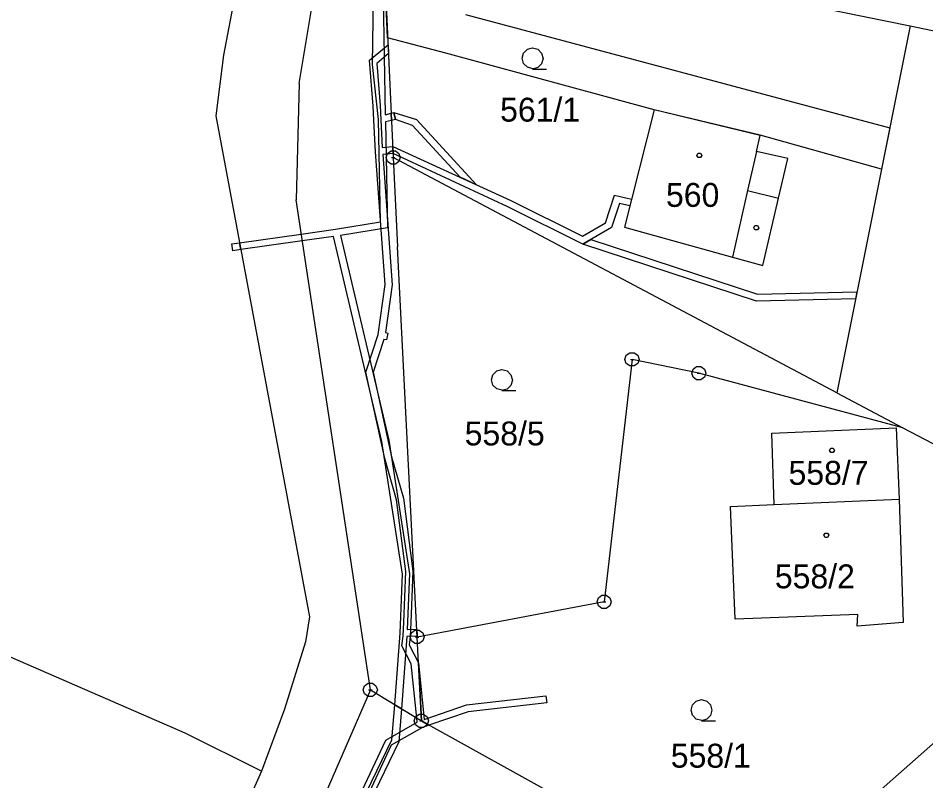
# Model space of a CAD drawing. Extents: x -759699 to -757730, y -1172308 to -1170857.
# Drawn here: x -759235.7 to -759171.2, y -1171629.6 to -1171575.4 of the extents above; entities that cross this region are included whole.
import ezdxf

# ---------------------------------------------------------------- set-up
doc = ezdxf.new("R2010")
doc.units = 0
for name, color, linetype in [('Vrstva 1', 7, 'Continuous'), ('Vrstva 12', 7, 'Continuous'), ('Vrstva 13', 7, 'Continuous'), ('Vrstva 2', 7, 'Continuous'), ('Vrstva 3', 7, 'Continuous'), ('Vrstva 4', 7, 'Continuous'), ('Vrstva 5', 7, 'Continuous'), ('Vrstva 8', 7, 'Continuous')]:
    doc.layers.add(name, color=color, linetype=linetype)

msp = doc.modelspace()

# ---------------------------------------------------------------- linework, layer by layer
at = {"layer": 'Vrstva 1'}
for p, q in [((-759215.76, -1171580.02), (-759212.95, -1171563.14)), ((-759209.89, -1171567.64), (-759209.07, -1171585.28)), ((-759188.19, -1171572.67), (-759172.32, -1171575.91)), ((-759220.33, -1171573.68), (-759221.15, -1171578)), ((-759172.32, -1171575.91), (-759177.54, -1171601.99)), ((-759172.32, -1171575.91), (-759169.31, -1171576.53)), ((-759221.15, -1171578), (-759221.68, -1171582.31)), ((-759215.76, -1171580.02), (-759215.98, -1171588.27)), ((-759190.52, -1171581.89), (-759192.62, -1171590.23)), ((-759182.99, -1171583.71), (-759190.52, -1171581.89)), ((-759221.68, -1171582.31), (-759215.03, -1171617.92)), ((-759183.25, -1171584.85), (-759182.99, -1171583.71)), ((-759209.07, -1171585.28), (-759208.77, -1171591.63)), ((-759177.54, -1171601.99), (-759209.07, -1171585.28)), ((-759181.01, -1171585.35), (-759183.25, -1171584.85)), ((-759181.67, -1171588.17), (-759181.01, -1171585.35)), ((-759210.7, -1171623.12), (-759215.98, -1171588.27)), ((-759182.78, -1171592.95), (-759181.67, -1171588.17)), ((-759192.62, -1171590.23), (-759184.96, -1171592.35)), ((-759207.37, -1171619.36), (-759208.77, -1171591.63)), ((-759184.96, -1171592.35), (-759182.78, -1171592.95)), ((-759192.09, -1171599.63), (-759194.07, -1171616.87)), ((-759187.34, -1171600.61), (-759192.09, -1171599.63)), ((-759172.84, -1171604.48), (-759187.34, -1171600.61)), ((-759177.54, -1171601.99), (-759172.84, -1171604.48)), ((-759182.15, -1171604.87), (-759173.32, -1171604.49)), ((-759173.32, -1171604.49), (-759173.1, -1171609.56)), ((-759172.84, -1171604.48), (-759155.62, -1171613.61)), ((-759181.99, -1171609.94), (-759182.15, -1171604.87)), ((-759223.87, -1171626.2), (-759264.92, -1171608.32)), ((-759181.99, -1171609.94), (-759173.1, -1171609.56)), ((-759173.1, -1171609.56), (-759172.82, -1171618.32)), ((-759185.09, -1171610.07), (-759181.99, -1171609.94)), ((-759184.77, -1171618.09), (-759185.09, -1171610.07)), ((-759183.56, -1171638.31), (-759155.62, -1171613.61)), ((-759194.07, -1171616.87), (-759207.37, -1171619.36)), ((-759215.03, -1171617.92), (-759215.32, -1171619.71)), ((-759176.04, -1171617.76), (-759184.77, -1171618.09)), ((-759176.08, -1171618.59), (-759176.04, -1171617.76)), ((-759172.82, -1171618.32), (-759176.08, -1171618.59)), ((-759207.07, -1171625.33), (-759207.37, -1171619.36)), ((-759215.32, -1171619.71), (-759216.8, -1171624.5)), ((-759210.7, -1171623.12), (-759215.69, -1171634.65)), ((-759210.7, -1171623.12), (-759207.07, -1171625.33)), ((-759216.8, -1171624.5), (-759218.43, -1171628.89)), ((-759207.07, -1171625.33), (-759183.56, -1171638.31)), ((-759218.43, -1171628.89), (-759223.87, -1171626.2)), ((-759218.43, -1171628.89), (-759222.99, -1171638.88))]:
    msp.add_line(p, q, dxfattribs=at)
at = {"layer": 'Vrstva 12'}
for p, q in [((-759190.52, -1171581.89), (-759192.62, -1171590.23)), ((-759182.99, -1171583.71), (-759190.52, -1171581.89)), ((-759183.25, -1171584.85), (-759182.99, -1171583.71)), ((-759183.25, -1171584.85), (-759183.88, -1171587.61)), ((-759183.88, -1171587.61), (-759184.96, -1171592.35)), ((-759192.62, -1171590.23), (-759184.96, -1171592.35)), ((-759182.15, -1171604.87), (-759173.32, -1171604.49)), ((-759173.32, -1171604.49), (-759173.1, -1171609.56)), ((-759181.99, -1171609.94), (-759182.15, -1171604.87)), ((-759181.99, -1171609.94), (-759173.1, -1171609.56)), ((-759181.99, -1171609.94), (-759173.1, -1171609.56)), ((-759173.1, -1171609.56), (-759172.82, -1171618.32)), ((-759185.09, -1171610.07), (-759181.99, -1171609.94)), ((-759184.77, -1171618.09), (-759185.09, -1171610.07)), ((-759176.04, -1171617.76), (-759184.77, -1171618.09)), ((-759176.08, -1171618.59), (-759176.04, -1171617.76)), ((-759172.82, -1171618.32), (-759176.08, -1171618.59))]:
    msp.add_line(p, q, dxfattribs=at)
at = {"layer": 'Vrstva 13'}
for p, q in [((-759210.55, -1171578.67), (-759210.39, -1171567.45)), ((-759209.89, -1171567.64), (-759209.65, -1171582.23)), ((-759209.47, -1171576.76), (-759209.61, -1171573.58)), ((-759203.93, -1171575.1), (-759173.77, -1171583.16)), ((-759205.34, -1171577.86), (-759209.47, -1171576.76)), ((-759210.75, -1171578.36), (-759209.44, -1171577.25)), ((-759209.44, -1171577.25), (-759209.41, -1171577.88)), ((-759209.41, -1171577.88), (-759210.23, -1171578.58)), ((-759190.51, -1171581.88), (-759205.34, -1171577.86)), ((-759210.51, -1171581.62), (-759210.75, -1171578.36)), ((-759210.12, -1171582.57), (-759210.55, -1171578.67)), ((-759210.23, -1171578.58), (-759210.01, -1171581.58)), ((-759210.45, -1171582.61), (-759210.51, -1171581.62)), ((-759210.01, -1171581.58), (-759209.95, -1171582.59)), ((-759209.65, -1171582.23), (-759209.22, -1171582.12)), ((-759209.22, -1171582.12), (-759209.03, -1171582.07)), ((-759209.19, -1171582.63), (-759209.22, -1171582.12)), ((-759209.22, -1171582.12), (-759209.19, -1171582.63)), ((-759209.03, -1171582.07), (-759208.9, -1171582.56)), ((-759209.03, -1171582.07), (-759207.41, -1171582.58)), ((-759208.9, -1171582.56), (-759209.03, -1171582.07)), ((-759182.99, -1171583.69), (-759190.51, -1171581.88)), ((-759210.34, -1171584.86), (-759210.45, -1171582.61)), ((-759209.98, -1171589.84), (-759210.12, -1171582.57)), ((-759209.95, -1171582.59), (-759209.85, -1171584.57)), ((-759209.19, -1171582.63), (-759209.62, -1171582.74)), ((-759209.62, -1171582.74), (-759209.48, -1171590.26)), ((-759208.9, -1171582.56), (-759209.19, -1171582.63)), ((-759207.71, -1171583), (-759208.9, -1171582.56)), ((-759207.41, -1171582.58), (-759203.14, -1171587.21)), ((-759204.32, -1171586.67), (-759207.71, -1171583)), ((-759173.77, -1171583.16), (-759174.36, -1171586.11)), ((-759174.36, -1171586.11), (-759182.99, -1171583.69)), ((-759209.85, -1171584.57), (-759209.11, -1171584.48)), ((-759209.11, -1171584.48), (-759209.08, -1171584.99)), ((-759209.11, -1171584.48), (-759200.71, -1171588.32)), ((-759209.08, -1171584.99), (-759209.11, -1171584.48)), ((-759209.64, -1171594.3), (-759210.34, -1171584.86)), ((-759209.08, -1171584.99), (-759209.82, -1171585.06)), ((-759209.82, -1171585.06), (-759209.14, -1171594.32)), ((-759200.93, -1171588.78), (-759209.08, -1171584.99)), ((-759203.14, -1171587.21), (-759204.32, -1171586.67)), ((-759193.97, -1171589.91), (-759193.33, -1171587.96)), ((-759193.33, -1171587.96), (-759192.12, -1171588.23)), ((-759200.71, -1171588.32), (-759195.61, -1171590.87)), ((-759192.99, -1171588.54), (-759193.55, -1171590.25)), ((-759192.24, -1171588.71), (-759192.99, -1171588.54)), ((-759192.12, -1171588.23), (-759192.24, -1171588.71)), ((-759195.59, -1171591.43), (-759200.93, -1171588.78)), ((-759213.17, -1171590.36), (-759209.98, -1171589.84)), ((-759195.61, -1171590.87), (-759193.97, -1171589.91)), ((-759215.61, -1171590.71), (-759213.17, -1171590.36)), ((-759209.48, -1171590.26), (-759212.83, -1171590.81)), ((-759193.55, -1171590.25), (-759195.59, -1171591.43)), ((-759220, -1171591.33), (-759215.61, -1171590.71)), ((-759215.54, -1171591.2), (-759219.9, -1171591.82)), ((-759213.32, -1171590.89), (-759215.54, -1171591.2)), ((-759209.89, -1171605.46), (-759213.32, -1171590.89)), ((-759212.83, -1171590.81), (-759209.39, -1171605.36)), ((-759195.59, -1171591.43), (-759195.01, -1171591.09)), ((-759195.01, -1171591.09), (-759183.17, -1171594.98)), ((-759220.54, -1171591.4), (-759220, -1171591.33)), ((-759220.47, -1171591.9), (-759220.54, -1171591.4)), ((-759219.9, -1171591.82), (-759220.47, -1171591.9)), ((-759220, -1171591.33), (-759219.9, -1171591.82)), ((-759219.9, -1171591.82), (-759220, -1171591.33)), ((-759183.25, -1171595.48), (-759195.59, -1171591.43)), ((-759210.15, -1171597.85), (-759209.64, -1171594.3)), ((-759209.14, -1171594.32), (-759209.63, -1171597.72)), ((-759183.17, -1171594.98), (-759176.11, -1171594.82)), ((-759176.11, -1171594.82), (-759176.21, -1171595.32)), ((-759176.21, -1171595.32), (-759183.25, -1171595.48)), ((-759211.01, -1171600.52), (-759210.15, -1171597.85)), ((-759209.74, -1171598.2), (-759210.49, -1171600.54)), ((-759209.55, -1171598.24), (-759209.74, -1171598.2)), ((-759209.63, -1171597.72), (-759209.45, -1171597.76)), ((-759209.45, -1171597.76), (-759209.55, -1171598.24)), ((-759209.68, -1171606.68), (-759211.01, -1171600.52)), ((-759210.49, -1171600.54), (-759209.2, -1171606.56)), ((-759209.39, -1171605.36), (-759207.91, -1171614.87)), ((-759208.41, -1171614.89), (-759209.89, -1171605.46)), ((-759208.84, -1171609.6), (-759209.68, -1171606.68)), ((-759209.2, -1171606.56), (-759208.34, -1171609.5)), ((-759208.17, -1171614.7), (-759208.84, -1171609.6)), ((-759208.34, -1171609.5), (-759207.67, -1171614.68)), ((-759208.58, -1171619.08), (-759208.41, -1171614.89)), ((-759208.33, -1171618.31), (-759208.17, -1171614.7)), ((-759207.91, -1171614.87), (-759208.07, -1171618.83)), ((-759207.67, -1171614.68), (-759207.83, -1171618.33)), ((-759208.37, -1171619.3), (-759208.33, -1171618.31)), ((-759208.07, -1171618.83), (-759207.4, -1171618.81)), ((-759207.83, -1171618.33), (-759207.87, -1171619.34)), ((-759207.4, -1171618.81), (-759207.37, -1171619.31)), ((-759208.97, -1171624.17), (-759208.58, -1171619.08)), ((-759208.1, -1171619.33), (-759208.49, -1171624.46)), ((-759208.47, -1171619.99), (-759208.37, -1171619.3)), ((-759207.37, -1171619.31), (-759208.1, -1171619.33)), ((-759207.87, -1171619.34), (-759207.95, -1171619.91)), ((-759207.8, -1171621.26), (-759208.47, -1171619.99)), ((-759207.95, -1171619.91), (-759207.28, -1171621.19)), ((-759207.4, -1171625.13), (-759207.8, -1171621.26)), ((-759207.28, -1171621.19), (-759207.07, -1171625.33)), ((-759207.07, -1171625.33), (-759207.28, -1171621.19)), ((-759207.28, -1171621.19), (-759206.88, -1171625.22)), ((-759203.86, -1171624.17), (-759198.22, -1171623.53)), ((-759198.16, -1171624.03), (-759203.74, -1171624.67)), ((-759198.22, -1171623.53), (-759198.16, -1171624.03)), ((-759209.17, -1171626.68), (-759208.97, -1171624.17)), ((-759208.49, -1171624.46), (-759208.97, -1171624.17)), ((-759208.97, -1171624.17), (-759208.49, -1171624.46)), ((-759208.49, -1171624.46), (-759208.67, -1171626.82)), ((-759206.88, -1171625.22), (-759203.86, -1171624.17)), ((-759203.74, -1171624.67), (-759206.53, -1171625.63)), ((-759209.59, -1171626.69), (-759207.37, -1171625.42)), ((-759207.07, -1171625.33), (-759207.4, -1171625.13)), ((-759207.37, -1171625.42), (-759207.4, -1171625.13)), ((-759207.4, -1171625.13), (-759207.07, -1171625.33)), ((-759207.07, -1171625.33), (-759206.53, -1171625.63)), ((-759206.53, -1171625.63), (-759207.07, -1171625.33)), ((-759207, -1171625.79), (-759209.21, -1171627.05)), ((-759206.53, -1171625.63), (-759207, -1171625.79)), ((-759213.6, -1171635.77), (-759209.17, -1171626.68)), ((-759212.22, -1171632.24), (-759209.59, -1171626.69)), ((-759208.67, -1171626.82), (-759213.16, -1171636.01)), ((-759209.21, -1171627.05), (-759211.76, -1171632.46))]:
    msp.add_line(p, q, dxfattribs=at)
at = {"layer": 'Vrstva 3'}
for points in [[(-759199.15, -1171578.96), (-759199.53, -1171578.86), (-759199.8, -1171578.59), (-759199.9, -1171578.22), (-759199.8, -1171577.85), (-759199.53, -1171577.58), (-759199.16, -1171577.48), (-759198.79, -1171577.58), (-759198.52, -1171577.85), (-759198.42, -1171578.23), (-759198.52, -1171578.61), (-759198.79, -1171578.88), (-759199.17, -1171578.98), (-759198.17, -1171578.98)], [(-759201.33, -1171601.82), (-759201.71, -1171601.72), (-759201.98, -1171601.45), (-759202.08, -1171601.08), (-759201.98, -1171600.71), (-759201.71, -1171600.44), (-759201.34, -1171600.34), (-759200.97, -1171600.44), (-759200.7, -1171600.71), (-759200.6, -1171601.09), (-759200.7, -1171601.47), (-759200.97, -1171601.74), (-759201.35, -1171601.84), (-759200.35, -1171601.84)], [(-759187.14, -1171625.29), (-759187.52, -1171625.19), (-759187.79, -1171624.92), (-759187.89, -1171624.55), (-759187.79, -1171624.18), (-759187.52, -1171623.91), (-759187.15, -1171623.81), (-759186.78, -1171623.91), (-759186.51, -1171624.18), (-759186.41, -1171624.56), (-759186.51, -1171624.94), (-759186.78, -1171625.21), (-759187.16, -1171625.31), (-759186.16, -1171625.31)]]:
    msp.add_lwpolyline(points, dxfattribs=at)
at = {"layer": 'Vrstva 4'}
for p, q in [((-759183.25, -1171584.85), (-759183.88, -1171587.61)), ((-759183.88, -1171587.61), (-759184.96, -1171592.35)), ((-759183.88, -1171587.61), (-759181.67, -1171588.17))]:
    msp.add_line(p, q, dxfattribs=at)
at = {"layer": 'Vrstva 5'}
for points in [[(-759187.22, -1171584.97), (-759187.13, -1171585.12), (-759187.22, -1171585.27), (-759187.4, -1171585.27), (-759187.49, -1171585.12), (-759187.4, -1171584.97)], [(-759183.17, -1171590.11), (-759183.08, -1171590.26), (-759183.17, -1171590.41), (-759183.35, -1171590.41), (-759183.44, -1171590.26), (-759183.35, -1171590.11)], [(-759177.78, -1171605.94), (-759177.69, -1171606.09), (-759177.78, -1171606.24), (-759177.96, -1171606.24), (-759178.05, -1171606.09), (-759177.96, -1171605.94)], [(-759178.19, -1171611.98), (-759178.1, -1171612.13), (-759178.19, -1171612.28), (-759178.37, -1171612.28), (-759178.46, -1171612.13), (-759178.37, -1171611.98)]]:
    msp.add_lwpolyline(points, close=True, dxfattribs=at)
at = {"layer": 'Vrstva 8'}
for p, q in [((-759209.19, -1171585.28), (-759208.95, -1171585.28)), ((-759192.21, -1171599.63), (-759191.97, -1171599.63)), ((-759187.46, -1171600.61), (-759187.22, -1171600.61)), ((-759194.19, -1171616.87), (-759193.95, -1171616.87)), ((-759207.49, -1171619.36), (-759207.25, -1171619.36)), ((-759210.82, -1171623.12), (-759210.58, -1171623.12)), ((-759207.19, -1171625.33), (-759206.95, -1171625.33))]:
    msp.add_line(p, q, dxfattribs=at)
for points in [[(-759208.92, -1171584.8), (-759208.67, -1171584.98), (-759208.57, -1171585.27), (-759208.67, -1171585.56), (-759208.92, -1171585.74), (-759209.23, -1171585.74), (-759209.48, -1171585.56), (-759209.58, -1171585.27), (-759209.48, -1171584.98), (-759209.23, -1171584.8)], [(-759191.94, -1171599.15), (-759191.69, -1171599.33), (-759191.59, -1171599.62), (-759191.69, -1171599.91), (-759191.94, -1171600.09), (-759192.25, -1171600.09), (-759192.5, -1171599.91), (-759192.6, -1171599.62), (-759192.5, -1171599.33), (-759192.25, -1171599.15)], [(-759187.19, -1171600.13), (-759186.94, -1171600.31), (-759186.84, -1171600.6), (-759186.94, -1171600.89), (-759187.19, -1171601.07), (-759187.5, -1171601.07), (-759187.75, -1171600.89), (-759187.85, -1171600.6), (-759187.75, -1171600.31), (-759187.5, -1171600.13)], [(-759193.92, -1171616.39), (-759193.67, -1171616.57), (-759193.57, -1171616.86), (-759193.67, -1171617.15), (-759193.92, -1171617.33), (-759194.23, -1171617.33), (-759194.48, -1171617.15), (-759194.58, -1171616.86), (-759194.48, -1171616.57), (-759194.23, -1171616.39)], [(-759207.22, -1171618.88), (-759206.97, -1171619.06), (-759206.87, -1171619.35), (-759206.97, -1171619.64), (-759207.22, -1171619.82), (-759207.53, -1171619.82), (-759207.78, -1171619.64), (-759207.88, -1171619.35), (-759207.78, -1171619.06), (-759207.53, -1171618.88)], [(-759210.55, -1171622.64), (-759210.3, -1171622.82), (-759210.2, -1171623.11), (-759210.3, -1171623.4), (-759210.55, -1171623.58), (-759210.86, -1171623.58), (-759211.11, -1171623.4), (-759211.21, -1171623.11), (-759211.11, -1171622.82), (-759210.86, -1171622.64)], [(-759206.92, -1171624.85), (-759206.67, -1171625.03), (-759206.57, -1171625.32), (-759206.67, -1171625.61), (-759206.92, -1171625.79), (-759207.23, -1171625.79), (-759207.48, -1171625.61), (-759207.58, -1171625.32), (-759207.48, -1171625.03), (-759207.23, -1171624.85)]]:
    msp.add_lwpolyline(points, close=True, dxfattribs=at)

# ---------------------------------------------------------------- texts
at = {"layer": 'Vrstva 2'}
for s, p in [('561/1', (-759201.474, -1171582.72)), ('560', (-759189.678, -1171588.78)), ('558/5', (-759203.991, -1171605.74)), ('558/7', (-759180.964, -1171608.54)), ('558/2', (-759181.937, -1171615.9)), ('558/1', (-759189.336, -1171628.65))]:
    msp.add_text(s, height=1.7, dxfattribs=at).set_placement(p)

doc.saveas('drawing.dxf')
